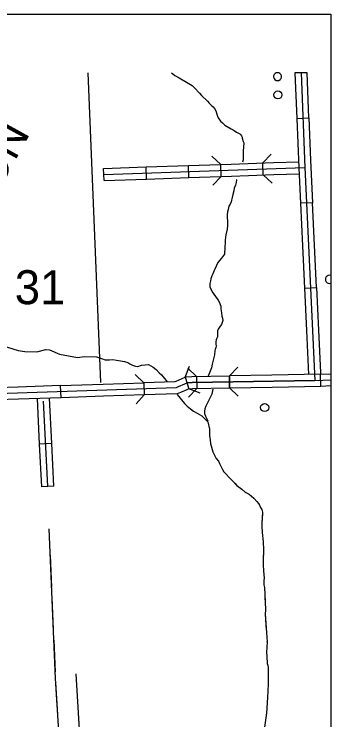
# Model space of a CAD drawing. Extents: x 309348 to 309445, y 336383 to 336484.
# Drawn here: x 309355.577 to 309356.364, y 336402.233 to 336403.988 of the extents above; entities that cross this region are included whole.
import ezdxf

# ---------------------------------------------------------------- set-up
doc = ezdxf.new("R2010")
doc.units = 0
doc.layers.add('R_Annotation', color=7, linetype='Continuous')
doc.layers.add('R_Border Notes', color=7, linetype='Continuous')

msp = doc.modelspace()

# ---------------------------------------------------------------- linework, layer by layer
at = {"layer": 'R_Annotation'}
for p, q in [((309356.2344, 336403.8418), (309356.2284, 336403.8418)), ((309356.2748, 336403.8418), (309356.2794, 336403.7285)), ((309356.3049, 336403.8418), (309356.2748, 336403.8418)), ((309356.3094, 336403.7297), (309356.3049, 336403.8418)), ((309356.0113, 336403.5812), (309356.0102, 336403.6112)), ((309356.0913, 336403.584), (309356.0902, 336403.614)), ((309356.1961, 336403.5876), (309356.1951, 336403.6176)), ((309355.8001, 336403.5739), (309355.7991, 336403.6039)), ((309355.9057, 336403.5776), (309355.9047, 336403.6076)), ((309356.3185, 336403.5187), (309356.2885, 336403.5173)), ((309356.3185, 336403.5187), (309356.3185, 336403.5187)), ((309356.2982, 336403.3063), (309356.3282, 336403.3076)), ((309356.2174, 336403.09), (309356.1118, 336403.0881)), ((309356.1123, 336403.0581), (309356.1118, 336403.0881)), ((309356.3381, 336403.0925), (309356.2174, 336403.09)), ((309356.3395, 336403.0628), (309356.3381, 336403.0925)), ((309356.2179, 336403.06), (309356.3395, 336403.0628)), ((309355.67, 336402.9195), (309355.64, 336402.918)), ((309355.6751, 336402.814), (309355.6451, 336402.8125))]:
    msp.add_line(p, q, dxfattribs=at)
for points in [[(309355.7922, 336403.0714), (309355.7609, 336403.8418)], [(309355.9679, 336403.8418), (309355.971, 336403.8389), (309355.9761, 336403.8347), (309355.9871, 336403.8296), (309356.019, 336403.8105), (309356.0249, 336403.8046), (309356.0372, 336403.7914), (309356.0427, 336403.7854), (309356.0572, 336403.7714), (309356.0618, 336403.7659), (309356.0669, 336403.7604), (309356.0712, 336403.757), (309356.0763, 336403.7506), (309356.0792, 336403.7443), (309356.0805, 336403.7392), (309356.0818, 336403.7337), (309356.0839, 336403.7298), (309356.0899, 336403.7218), (309356.0945, 336403.7171), (309356.1005, 336403.7116), (309356.1162, 336403.7027), (309356.1234, 336403.698), (309356.1293, 336403.6942), (309356.1374, 336403.6899), (309356.1404, 336403.6874), (309356.1416, 336403.6848), (309356.1433, 336403.6819), (309356.1438, 336403.6789), (309356.1463, 336403.6712), (309356.1476, 336403.6678), (309356.1459, 336403.6466), (309356.1459, 336403.6352), (309356.1463, 336403.6301), (309356.1463, 336403.6254), (309356.1442, 336403.6197)], [(309356.2898, 336403.8418), (309356.2994, 336403.6062), (309356.3238, 336403.0769), (309356.3641, 336403.0785)], [(309356.2794, 336403.7285), (309356.2794, 336403.7285), (309356.3094, 336403.7297)], [(309356.2794, 336403.7285), (309356.2844, 336403.6055)], [(309356.3094, 336403.7297), (309356.3137, 336403.6241)], [(309356.0683, 336403.6345), (309356.0902, 336403.614)], [(309356.1951, 336403.6176), (309356.2156, 336403.6396)], [(309355.9047, 336403.6076), (309356.0102, 336403.6112)], [(309356.0102, 336403.6112), (309356.1158, 336403.6149)], [(309356.1158, 336403.6149), (309356.2214, 336403.6185)], [(309356.2214, 336403.6185), (309356.2838, 336403.6207)], [(309356.3137, 336403.6241), (309356.3144, 336403.6069), (309356.3185, 336403.5187)], [(309355.7991, 336403.6039), (309355.9047, 336403.6076)], [(309355.7996, 336403.5889), (309356.2994, 336403.6062)], [(309356.2844, 336403.6055), (309356.2885, 336403.5173)], [(309355.8001, 336403.5739), (309355.9057, 336403.5776)], [(309355.9057, 336403.5776), (309356.0113, 336403.5812)], [(309356.0113, 336403.5812), (309356.1168, 336403.5849)], [(309356.1299, 336403.5766), (309356.1293, 336403.5753), (309356.1285, 336403.5689), (309356.1268, 336403.5626), (309356.1238, 336403.5549), (309356.1225, 336403.5481), (309356.1204, 336403.5392), (309356.1187, 336403.532), (309356.1174, 336403.5248), (309356.1162, 336403.5205), (309356.1136, 336403.5154), (309356.1107, 336403.5099), (309356.1085, 336403.5018), (309356.1073, 336403.4963), (309356.1064, 336403.4887), (309356.1064, 336403.4798), (309356.1073, 336403.4751), (309356.1073, 336403.4679), (309356.1073, 336403.4624), (309356.106, 336403.453), (309356.103, 336403.4386), (309356.1013, 336403.4258), (309356.1009, 336403.4199), (309356.1005, 336403.408), (309356.0992, 336403.3906), (309356.0924, 336403.3808), (309356.0831, 336403.3702), (309356.0754, 336403.3537), (309356.0741, 336403.3498), (309356.0707, 336403.3414), (309356.0682, 336403.3367), (309356.0657, 336403.3295), (309356.0644, 336403.3244), (309356.0635, 336403.318), (309356.0635, 336403.3095), (309356.0691, 336403.2972), (309356.0771, 336403.2853), (309356.0839, 336403.2764), (309356.0873, 336403.2709), (309356.089, 336403.2654), (309356.0903, 336403.2611), (309356.0907, 336403.2547), (309356.092, 336403.245), (309356.0932, 336403.2369), (309356.0945, 336403.2314), (309356.0954, 336403.2254), (309356.092, 336403.2157), (309356.089, 336403.2114), (309356.0856, 336403.2068), (309356.0835, 336403.2042), (309356.0822, 336403.2004), (309356.0818, 336403.1966), (309356.0818, 336403.1894), (309356.0822, 336403.1851), (309356.0797, 336403.1804), (309356.0792, 336403.1779), (309356.0784, 336403.1728), (309356.0784, 336403.1681), (309356.0788, 336403.1622)], [(309356.0913, 336403.584), (309356.0708, 336403.5621)], [(309356.1168, 336403.5849), (309356.2224, 336403.5886)], [(309356.2181, 336403.5672), (309356.1961, 336403.5876)], [(309356.2224, 336403.5886), (309356.2851, 336403.5907)], [(309356.2885, 336403.5173), (309356.2934, 336403.4118)], [(309356.3233, 336403.4132), (309356.3185, 336403.5187)], [(309356.2934, 336403.4118), (309356.2982, 336403.3063)], [(309356.3282, 336403.3076), (309356.3233, 336403.4132)], [(309356.2982, 336403.3063), (309356.3031, 336403.2007)], [(309356.3282, 336403.3076), (309356.3331, 336403.2021)], [(309356.3031, 336403.2007), (309356.3081, 336403.0916)], [(309356.3331, 336403.2021), (309356.3379, 336403.0966)], [(309355.3113, 336403.1593), (309355.3161, 336403.154), (309355.3188, 336403.1519), (309355.3283, 336403.1487), (309355.3416, 336403.1513), (309355.3565, 336403.1572), (309355.374, 336403.1598), (309355.3921, 336403.1609), (309355.4272, 336403.1588), (309355.4506, 336403.1577), (309355.4729, 336403.154), (309355.4984, 336403.154), (309355.5244, 336403.1588), (309355.5436, 336403.1609), (309355.56, 336403.1593), (309355.5866, 336403.1513), (309355.6036, 336403.1487), (309355.6328, 336403.1481), (309355.6552, 336403.154), (309355.6647, 336403.1524), (309355.6897, 336403.1423), (309355.7338, 336403.1338), (309355.746, 336403.1354), (309355.7524, 336403.1359)], [(309356.0788, 336403.1622), (309356.078, 336403.1584), (309356.0775, 336403.1562), (309356.0763, 336403.1533), (309356.0754, 336403.1499), (309356.0745, 336403.1407)], [(309356.0745, 336403.1407), (309356.0691, 336403.1172), (309356.0669, 336403.1079), (309356.0625, 336403.0954), (309356.0593, 336403.0877)], [(309355.7524, 336403.1359), (309355.7815, 336403.1358), (309355.794, 336403.1309), (309355.8033, 336403.1281), (309355.8137, 336403.1276), (309355.8224, 336403.1287), (309355.8312, 336403.127), (309355.8508, 336403.1238), (309355.859, 336403.121), (309355.8644, 336403.1183), (309355.871, 336403.1145), (309355.8781, 336403.1123), (309355.8841, 336403.1112), (309355.8934, 336403.1145), (309355.9021, 336403.1156), (309355.9108, 336403.1161), (309355.9168, 336403.1134), (309355.9223, 336403.1096), (309355.9299, 336403.1041), (309355.937, 336403.0959), (309355.943, 336403.0905), (309355.9501, 336403.0812), (309355.9545, 336403.0763), (309355.9572, 336403.073)], [(309356.002, 336403.0845), (309356.013, 336403.1124)], [(309356.0084, 336403.1075), (309356.03, 336403.0866)], [(309356.1118, 336403.0881), (309356.1326, 336403.1097)], [(309355.8771, 336403.0912), (309355.8991, 336403.0708)], [(309356.0004, 336403.0838), (309356.0042, 336403.0855), (309356.0186, 336403.0864), (309356.1118, 336403.0881)], [(309356.002, 336403.0845), (309356.011, 336403.0561)], [(309356.03, 336403.0866), (309356.0305, 336403.0566)], [(309356.1118, 336403.0881), (309356.1123, 336403.0581), (309356.2179, 336403.06)], [(309356.3379, 336403.0966), (309356.3381, 336403.0925), (309356.3641, 336403.0935)], [(309356.3238, 336403.0769), (309356.0192, 336403.0714), (309356.0078, 336403.0707), (309355.9998, 336403.0671), (309355.9843, 336403.0605), (309355.9792, 336403.0585), (309355.1152, 336403.0289)], [(309356.0009, 336403.084), (309355.9938, 336403.0809), (309355.9786, 336403.0744), (309355.9761, 336403.0734), (309355.8991, 336403.0708)], [(309356.0065, 336403.0701), (309356.0078, 336403.0707), (309356.0192, 336403.0714), (309356.3238, 336403.0769)], [(309355.5867, 336403.06), (309355.4811, 336403.0564)], [(309355.6922, 336403.0637), (309355.5867, 336403.06)], [(309356.011, 336403.0561), (309356.0058, 336403.0533), (309355.99, 336403.0467), (309355.9823, 336403.0436), (309355.9001, 336403.0408)], [(309356.0305, 336403.0566), (309356.0097, 336403.035)], [(309356.0389, 336403.0451), (309356.011, 336403.0561)], [(309356.0115, 336403.0559), (309356.0198, 336403.0564), (309356.1123, 336403.0581)], [(309356.0706, 336403.055), (309356.0682, 336403.0426), (309356.0594, 336403.0246), (309356.0534, 336403.0126), (309356.0507, 336403.006), (309356.0496, 336403), (309356.0496, 336402.9946), (309356.0523, 336402.9875), (309356.0583, 336402.9766)], [(309356.1339, 336403.0373), (309356.1123, 336403.0581)], [(309356.3395, 336403.0628), (309356.3641, 336403.0637)], [(309355.6933, 336403.0337), (309355.5877, 336403.03)], [(309355.64, 336402.918), (309355.6346, 336403.0317)], [(309355.67, 336402.9195), (309355.6646, 336403.0327)], [(309355.9001, 336403.0408), (309355.8796, 336403.0188)], [(309355.9823, 336403.0419), (309356.0003, 336403.0195), (309356.0069, 336403.0124), (309356.0151, 336403.0059), (309356.0227, 336402.9999), (309356.0314, 336402.995), (309356.0429, 336402.989), (309356.0584, 336402.9734)], [(309355.5877, 336403.03), (309355.4821, 336403.0264)], [(309355.6601, 336402.8132), (309355.6499, 336403.0255)], [(309356.0584, 336402.9734), (309356.0627, 336402.9558), (309356.0627, 336402.9478), (309356.0627, 336402.9389), (309356.064, 336402.9291), (309356.0652, 336402.9193), (309356.0665, 336402.9142), (309356.0686, 336402.9053), (309356.0707, 336402.8994), (309356.0737, 336402.8922), (309356.0792, 336402.8824), (309356.0843, 336402.876), (309356.0873, 336402.8701), (309356.0949, 336402.8552), (309356.0983, 336402.8497), (309356.1039, 336402.8438), (309356.1111, 336402.8353), (309356.1196, 336402.8268), (309356.1302, 336402.8157), (309356.1425, 336402.806), (309356.1506, 336402.7992), (309356.1607, 336402.7937), (309356.1726, 336402.7835), (309356.1798, 336402.7758), (309356.1841, 336402.7707), (309356.1866, 336402.7665), (309356.1892, 336402.761), (309356.1922, 336402.7559), (309356.1939, 336402.7491), (309356.1926, 336402.7215), (309356.1922, 336402.7143), (309356.193, 336402.6986), (309356.1956, 336402.6752), (309356.1968, 336402.6553), (309356.1968, 336402.6472), (309356.196, 336402.6378), (309356.1956, 336402.6183), (309356.1964, 336402.6035), (309356.1981, 336402.5852), (309356.1973, 336402.5788), (309356.1977, 336402.5682), (309356.1989, 336402.5614), (309356.2006, 336402.5258), (309356.2015, 336402.5054), (309356.2011, 336402.4965), (309356.2053, 336402.4264), (309356.204, 336402.4001), (309356.2049, 336402.3908), (309356.2053, 336402.3725), (309356.2074, 336402.3674), (309356.2083, 336402.3627), (309356.2083, 336402.3211), (309356.2062, 336402.2883), (309356.2038, 336402.2495), (309356.1847, 336402.1141)], [(309356.0584, 336402.9734), (309356.0627, 336402.9558), (309356.0627, 336402.9478), (309356.0627, 336402.9389), (309356.0633, 336402.9344)], [(309355.6451, 336402.8125), (309355.64, 336402.918)], [(309355.6751, 336402.814), (309355.67, 336402.9195)], [(309356.0679, 336402.9084), (309356.0686, 336402.9053), (309356.0707, 336402.8994), (309356.0737, 336402.8922), (309356.0792, 336402.8824), (309356.0843, 336402.876), (309356.0873, 336402.8701), (309356.0949, 336402.8552), (309356.0983, 336402.8497), (309356.1039, 336402.8438), (309356.1068, 336402.8402)], [(309356.125, 336402.8211), (309356.1302, 336402.8157), (309356.1425, 336402.806), (309356.1506, 336402.7992), (309356.1607, 336402.7937), (309356.1726, 336402.7835), (309356.1798, 336402.7758), (309356.1841, 336402.7707), (309356.1847, 336402.7698)], [(309356.1937, 336402.7455), (309356.1926, 336402.7215), (309356.1922, 336402.7143), (309356.193, 336402.6986), (309356.1956, 336402.6752), (309356.1961, 336402.6665)], [(309355.6632, 336402.7078), (309355.679, 336402.3352), (309355.6875, 336402.1915), (309355.693, 336402.0854)], [(309355.6632, 336402.7078), (309355.6649, 336402.6683)], [(309355.666, 336402.6419), (309355.6694, 336402.5627)], [(309356.1962, 336402.6401), (309356.196, 336402.6378), (309356.1956, 336402.6183), (309356.1964, 336402.6035), (309356.1981, 336402.5852), (309356.1973, 336402.5788), (309356.1977, 336402.5682), (309356.1989, 336402.5614), (309356.199, 336402.5612)], [(309355.6705, 336402.5363), (309355.6738, 336402.4572)], [(309356.2002, 336402.5348), (309356.2006, 336402.5258), (309356.2015, 336402.5054), (309356.2011, 336402.4965), (309356.2035, 336402.4557)], [(309355.675, 336402.4308), (309355.6783, 336402.3516)], [(309356.2051, 336402.4293), (309356.2053, 336402.4264), (309356.204, 336402.4001), (309356.2049, 336402.3908), (309356.2049, 336402.3898)], [(309356.2049, 336402.3898), (309356.2053, 336402.3725), (309356.2074, 336402.3674), (309356.2083, 336402.3627), (309356.2083, 336402.3507)], [(309355.7301, 336402.3468), (309355.7462, 336402.0701)], [(309355.6796, 336402.3253), (309355.6843, 336402.2462)], [(309356.2083, 336402.3243), (309356.2083, 336402.3211), (309356.2062, 336402.2883), (309356.2038, 336402.2495), (309356.2032, 336402.2452)]]:
    msp.add_lwpolyline(points, dxfattribs=at)
msp.add_lwpolyline([(309355.7978, 336403.0673), (309355.8991, 336403.0708), (309355.9001, 336403.0408), (309355.7989, 336403.0373), (309355.6933, 336403.0337), (309355.6922, 336403.0637)], close=True, dxfattribs=at)
for centre in [(309356.2323, 336403.7869), (309356.1994, 336403.0093)]:
    msp.add_circle(centre, 0.01, dxfattribs=at)
for centre, start, end in [((309356.2314, 336403.8323), 107.3841, 72.6159), ((309356.3604, 336403.3281), 68.2599, 291.7401)]:
    msp.add_arc(centre, 0.01, start, end, dxfattribs=at)
at = {"layer": 'R_Border Notes'}
for p, q in [((309347.6607, 336403.9877), (309356.3641, 336403.9877)), ((309356.3641, 336403.9877), (309356.3641, 336395.7269))]:
    msp.add_line(p, q, dxfattribs=at)

# ---------------------------------------------------------------- texts
at = {"layer": 'R_Annotation'}
msp.add_text('UNION', height=0.08451, rotation=61.0076, dxfattribs=at).set_placement((309355.4413, 336403.3735))
msp.add_text('31', height=0.08451, dxfattribs=at).set_placement((309355.5782, 336403.2663))

doc.saveas('drawing.dxf')
